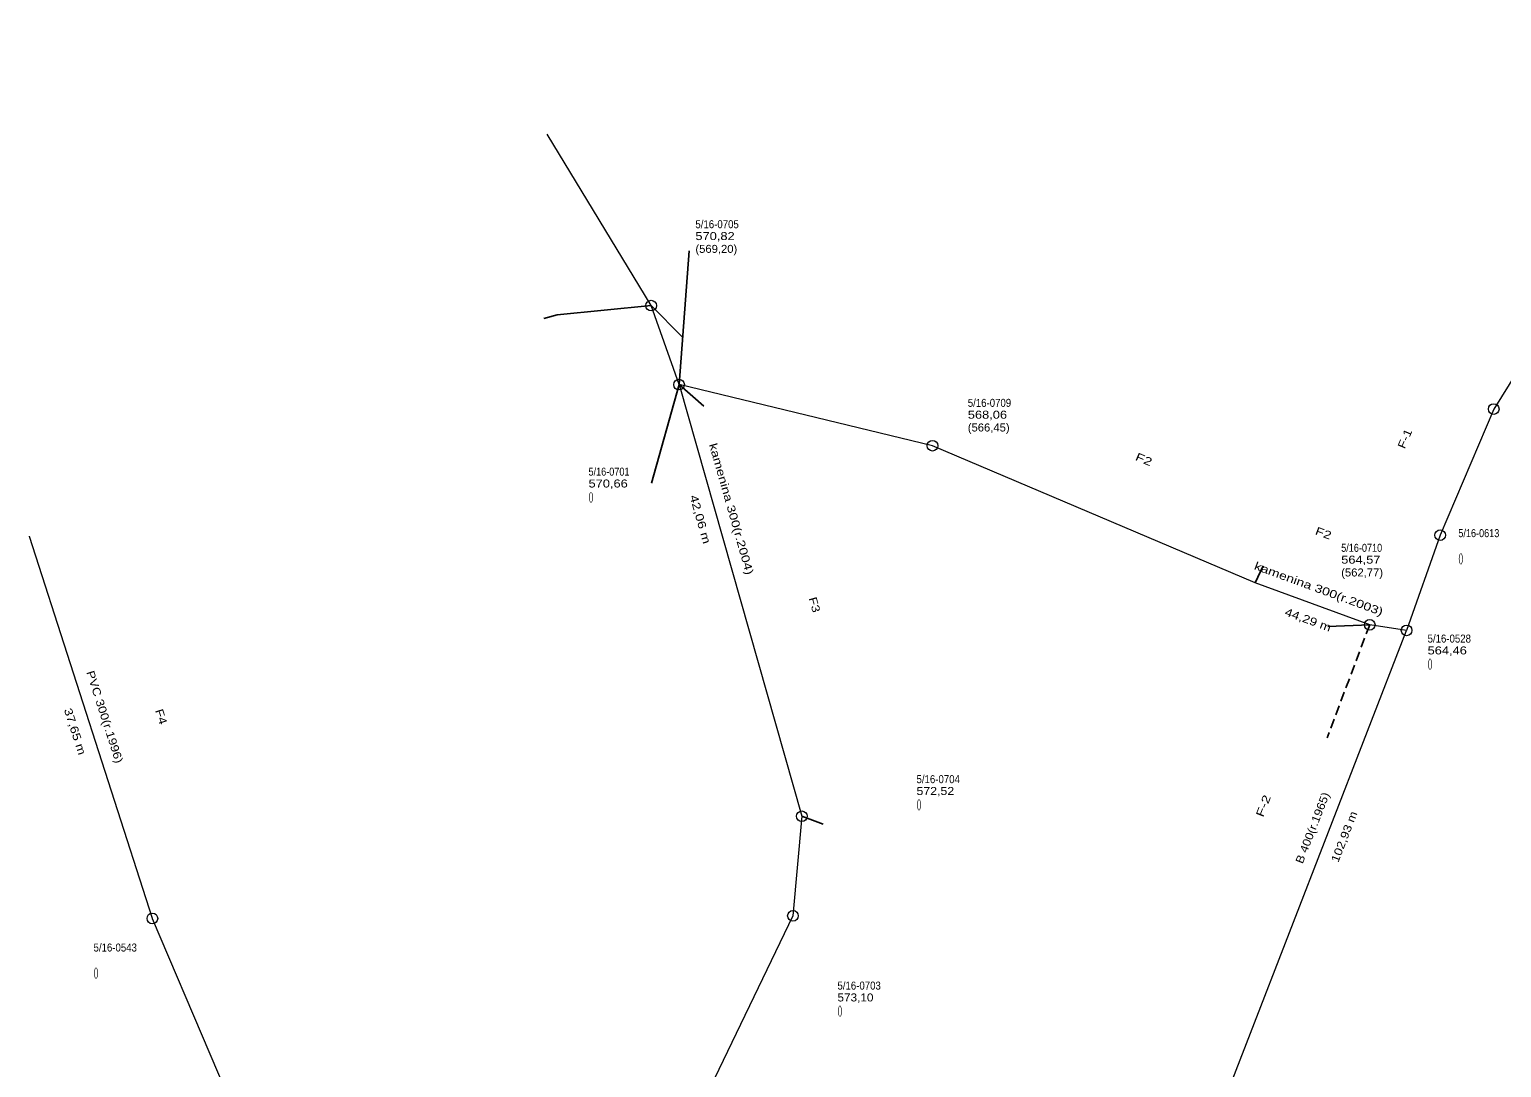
# Model space of a CAD drawing. Extents: x -710854 to -709799, y -1117012 to -1115891.
# Drawn here: x -710656 to -710518.1, y -1116723.5 to -1116626.2 of the extents above; entities that cross this region are included whole.
import ezdxf
from ezdxf.enums import TextEntityAlignment as Align

# ---------------------------------------------------------------- set-up
doc = ezdxf.new("R2010")
doc.units = 0
doc.header["$LTSCALE"] = 0.3
doc.linetypes.add('MEDIUM_DASHED', pattern=[4.5, 3, -1.5])
for name, color, linetype, lineweight in [('35', 7, 'Continuous', 25), ('38', 7, 'Continuous', 13), ('44', 7, 'Continuous', 13)]:
    doc.layers.add(name, color=color, linetype=linetype, lineweight=lineweight)
doc.layers.add('48', color=7, linetype='Continuous')

msp = doc.modelspace()

# ---------------------------------------------------------------- linework, layer by layer
at = {"layer": '35'}
for p, q in [((-710595.15, -1116659.452), (-710594.211, -1116646.911)), ((-710597.761, -1116652.051), (-710594.87, -1116654.96)), ((-710595.15, -1116659.45), (-710597.73, -1116668.7)), ((-710595.15, -1116659.45), (-710592.81, -1116661.48)), ((-710541.14, -1116678.04), (-710540.401, -1116676.426)), ((-710530.421, -1116681.971), (-710534.35, -1116682.12)), ((-710583.641, -1116699.911), (-710581.63, -1116700.65))]:
    msp.add_line(p, q, dxfattribs=at)
at = {"layer": '35', "linetype": 'MEDIUM_DASHED'}
msp.add_line((-710530.42, -1116681.97), (-710534.41, -1116692.551), dxfattribs=at)
at = {"layer": '35'}
msp.add_lwpolyline([(-710597.76, -1116652.051), (-710606.57, -1116652.9), (-710607.835, -1116653.27)], dxfattribs=at)
at = {"layer": '38'}
for p, q in [((-710464.49, -1116574.62), (-710518.8, -1116661.74)), ((-710597.76, -1116652.051), (-710607.501, -1116635.971)), ((-710595.15, -1116659.452), (-710597.76, -1116652.051)), ((-710571.391, -1116665.18), (-710595.15, -1116659.452)), ((-710518.8, -1116661.74), (-710523.82, -1116673.568)), ((-710583.64, -1116699.911), (-710584.471, -1116709.24))]:
    msp.add_line(p, q, dxfattribs=at)
for points in [[(-710595.15, -1116659.452), (-710583.64, -1116699.91), (-710583.64, -1116699.911)], [(-710530.42, -1116681.97), (-710541.141, -1116678.041), (-710571.391, -1116665.18)], [(-710644.507, -1116709.488), (-710656.015, -1116673.685), (-710656.02, -1116673.67), (-710656.028, -1116673.645)], [(-710523.82, -1116673.568), (-710526.959, -1116682.488), (-710530.42, -1116681.97)], [(-710582.15, -1116765.12), (-710548.91, -1116739.11), (-710526.959, -1116682.488)], [(-710633.69, -1116734.899), (-710644.497, -1116709.517), (-710644.5, -1116709.51), (-710644.507, -1116709.488)], [(-710584.471, -1116709.24), (-710584.471, -1116709.241), (-710593.03, -1116727.01), (-710593.031, -1116727.011)]]:
    msp.add_lwpolyline(points, dxfattribs=at)
at = {"layer": '44'}
for centre in [(-710597.76, -1116652.051), (-710595.15, -1116659.452), (-710518.8, -1116661.74), (-710571.391, -1116665.18), (-710523.82, -1116673.568), (-710530.42, -1116681.97), (-710526.959, -1116682.488), (-710583.64, -1116699.911), (-710644.507, -1116709.488), (-710584.471, -1116709.24)]:
    msp.add_circle(centre, 0.5, dxfattribs=at)

# ---------------------------------------------------------------- texts
at = {"layer": '48'}
for s, width, p in [('5/16-0705', 0.9, (-710593.614, -1116644.795)), ('570,82 ', 1.2, (-710593.614, -1116645.905)), ('(569,20)', 1.05, (-710593.614, -1116647.105)), ('5/16-0709', 0.9, (-710568.087, -1116661.538)), ('568,06 ', 1.2, (-710568.087, -1116662.648)), ('(566,45)', 1.05, (-710568.087, -1116663.848)), ('5/16-0701', 0.85, (-710603.632, -1116667.988)), ('570,66 ', 1.2, (-710603.632, -1116669.098)), ('()', 0.7, (-710603.632, -1116670.298)), ('5/16-0613', 0.85, (-710522.112, -1116673.752)), ('5/16-0710', 0.85, (-710533.091, -1116675.125)), ('564,57 ', 1.2, (-710533.091, -1116676.235)), ('(562,77)', 1.05, (-710533.091, -1116677.435)), ('()', 0.7, (-710522.112, -1116676.062)), ('5/16-0528', 0.9, (-710524.994, -1116683.634)), ('564,46 ', 1.2, (-710524.994, -1116684.744)), ('()', 0.7, (-710524.994, -1116685.944)), ('5/16-0704', 0.9, (-710572.891, -1116696.809)), ('572,52 ', 1.15, (-710572.891, -1116697.919)), ('()', 0.7, (-710572.891, -1116699.119)), ('5/16-0543', 0.9, (-710650.019, -1116712.591)), ('()', 0.7, (-710650.019, -1116714.901)), ('5/16-0703', 0.9, (-710580.302, -1116716.159)), ('573,10 ', 1.1, (-710580.302, -1116717.269)), ('()', 0.7, (-710580.302, -1116718.469))]:
    msp.add_text(s, height=0.75, dxfattribs=dict(at, width=width)).set_placement(p)
for s, rotation, width, p in [('F-1', 67, 1.25, (-710526.7777, -1116664.666)), ('kamenina 300(r.2004)', 285.88, 1.3, (-710590.5995, -1116671.2074)), ('F2', 336.97, 1.35, (-710551.7282, -1116666.8026)), ('42,06 m', 285.88, 1.3, (-710593.5161, -1116672.1754)), ('F2', 339.87, 1.3, (-710534.8816, -1116673.7306)), ('kamenina 300(r.2003)', 339.87, 1.3, (-710535.3216, -1116678.9378)), ('F3', 285.88, 1.25, (-710582.8067, -1116680.1834)), ('44,29 m', 339.87, 1.25, (-710536.3206, -1116681.841)), ('PVC 300(r.1996)', 287.82, 1.2, (-710649.3253, -1116690.7077)), ('37,65 m', 287.82, 1.25, (-710652.1091, -1116692.0782)), ('F4', 287.82, 1.25, (-710644.0362, -1116690.6912)), ('F-2', 68.81, 1.4, (-710540.0377, -1116699.071)), ('B 400(r.1965)', 68.81, 1.15, (-710535.4315, -1116701.133)), ('102,93 m', 68.81, 1.2, (-710532.4605, -1116701.963))]:
    msp.add_text(s, height=0.75, rotation=rotation, dxfattribs=dict(at, width=width)).set_placement(p, align=Align.CENTER)

doc.saveas('drawing.dxf')
